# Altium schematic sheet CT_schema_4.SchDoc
size 578 x 363 mm
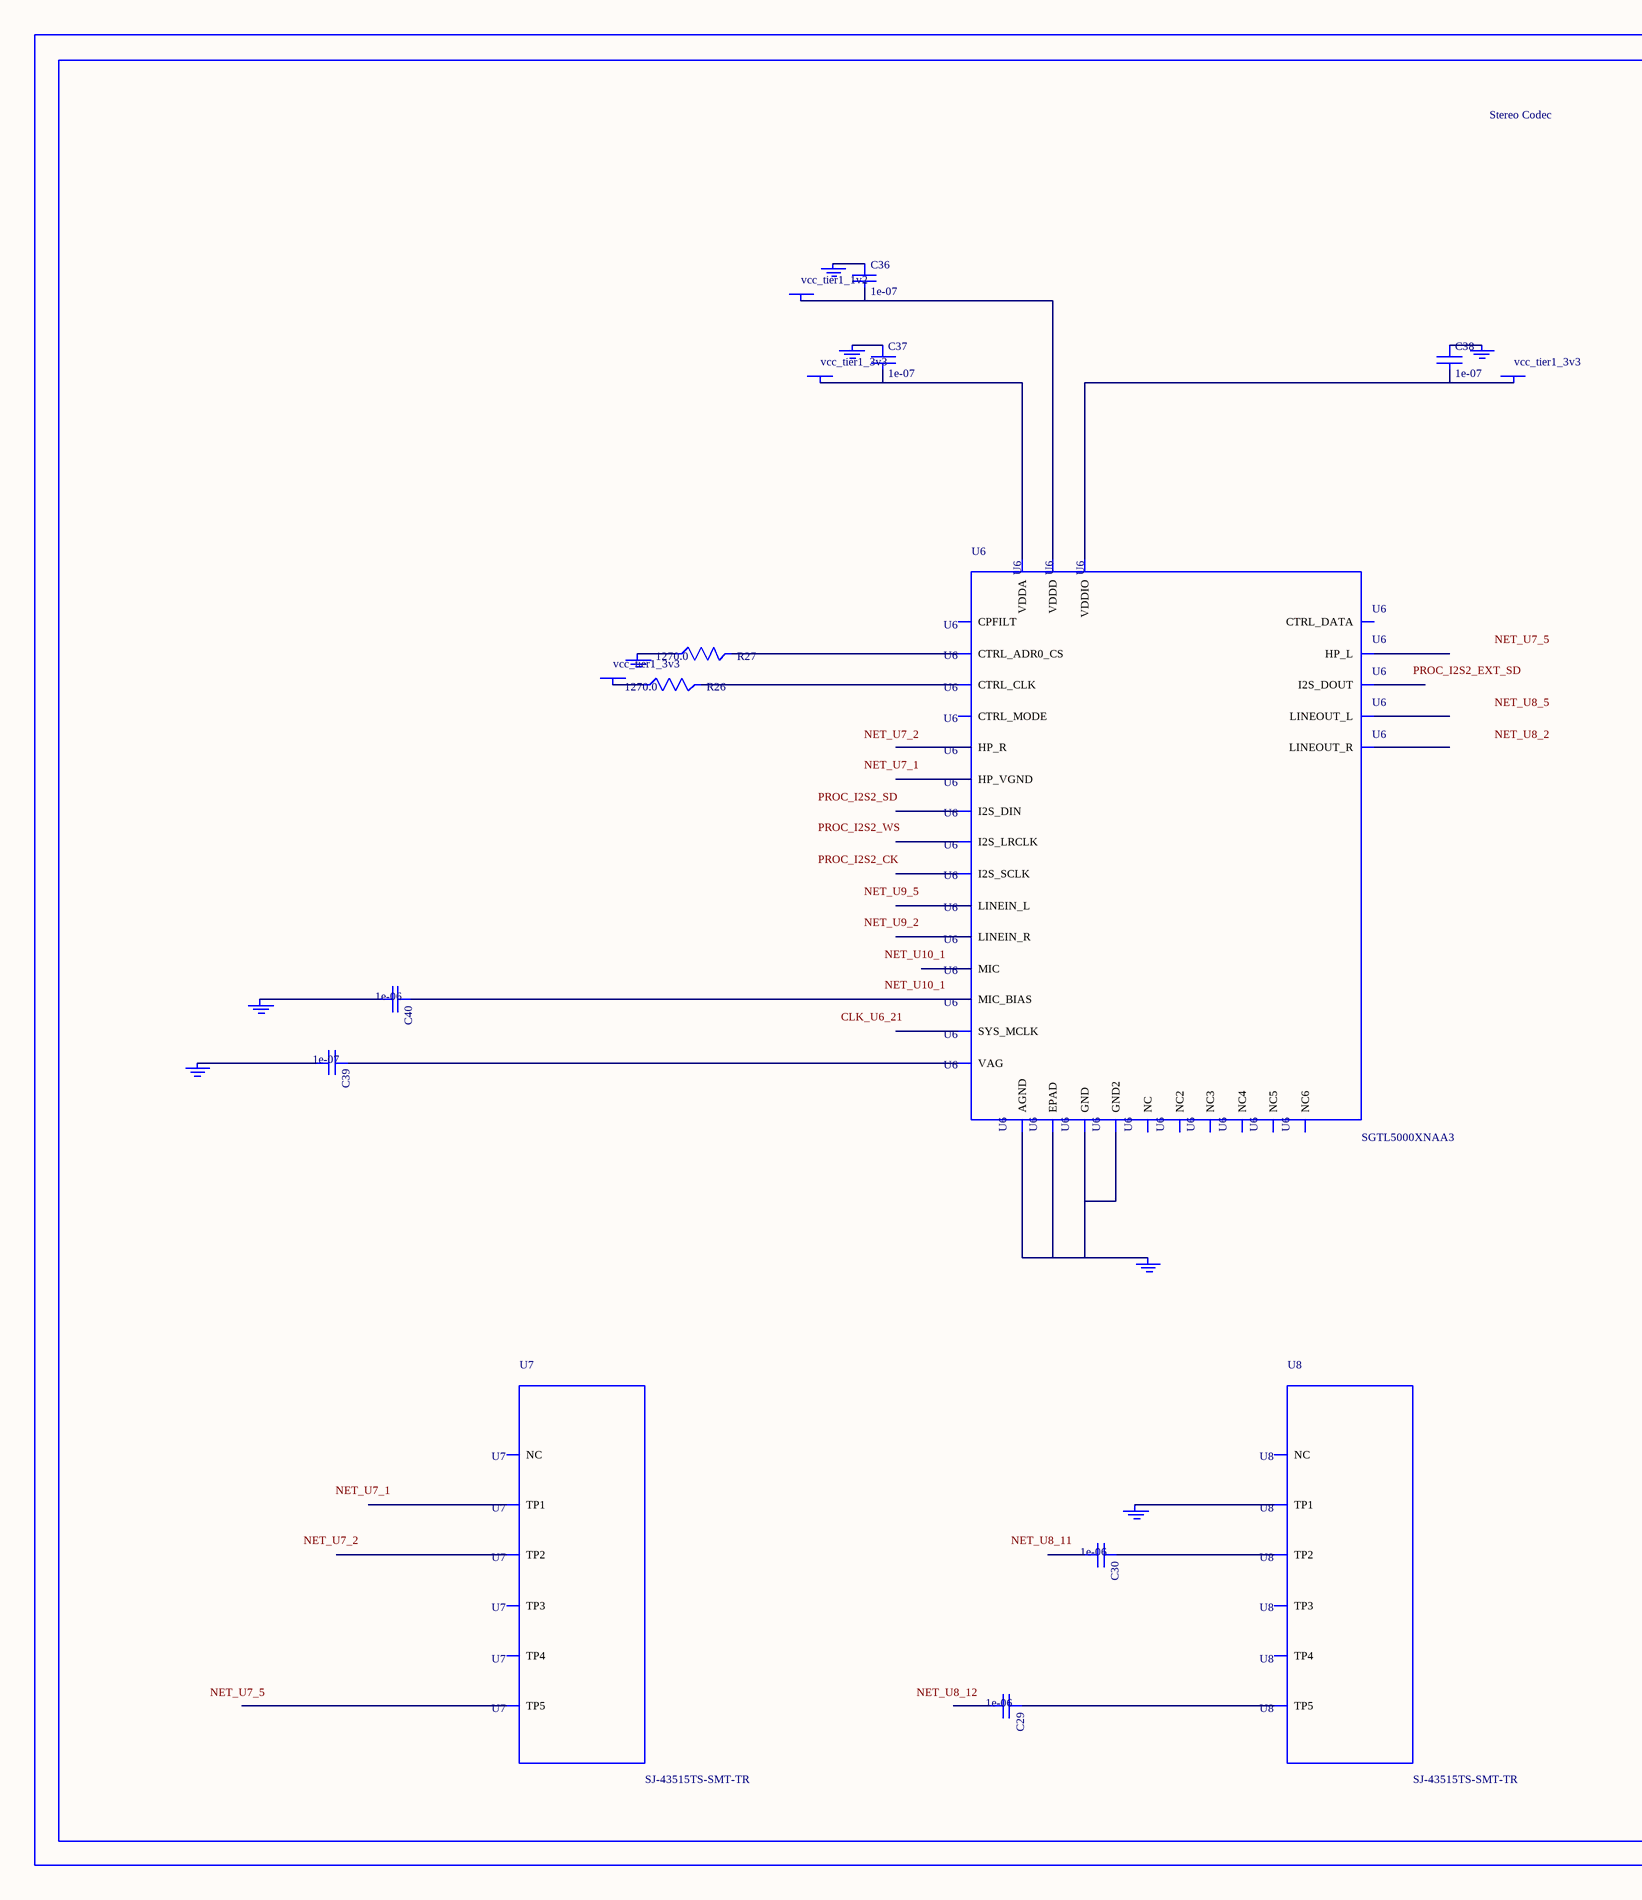
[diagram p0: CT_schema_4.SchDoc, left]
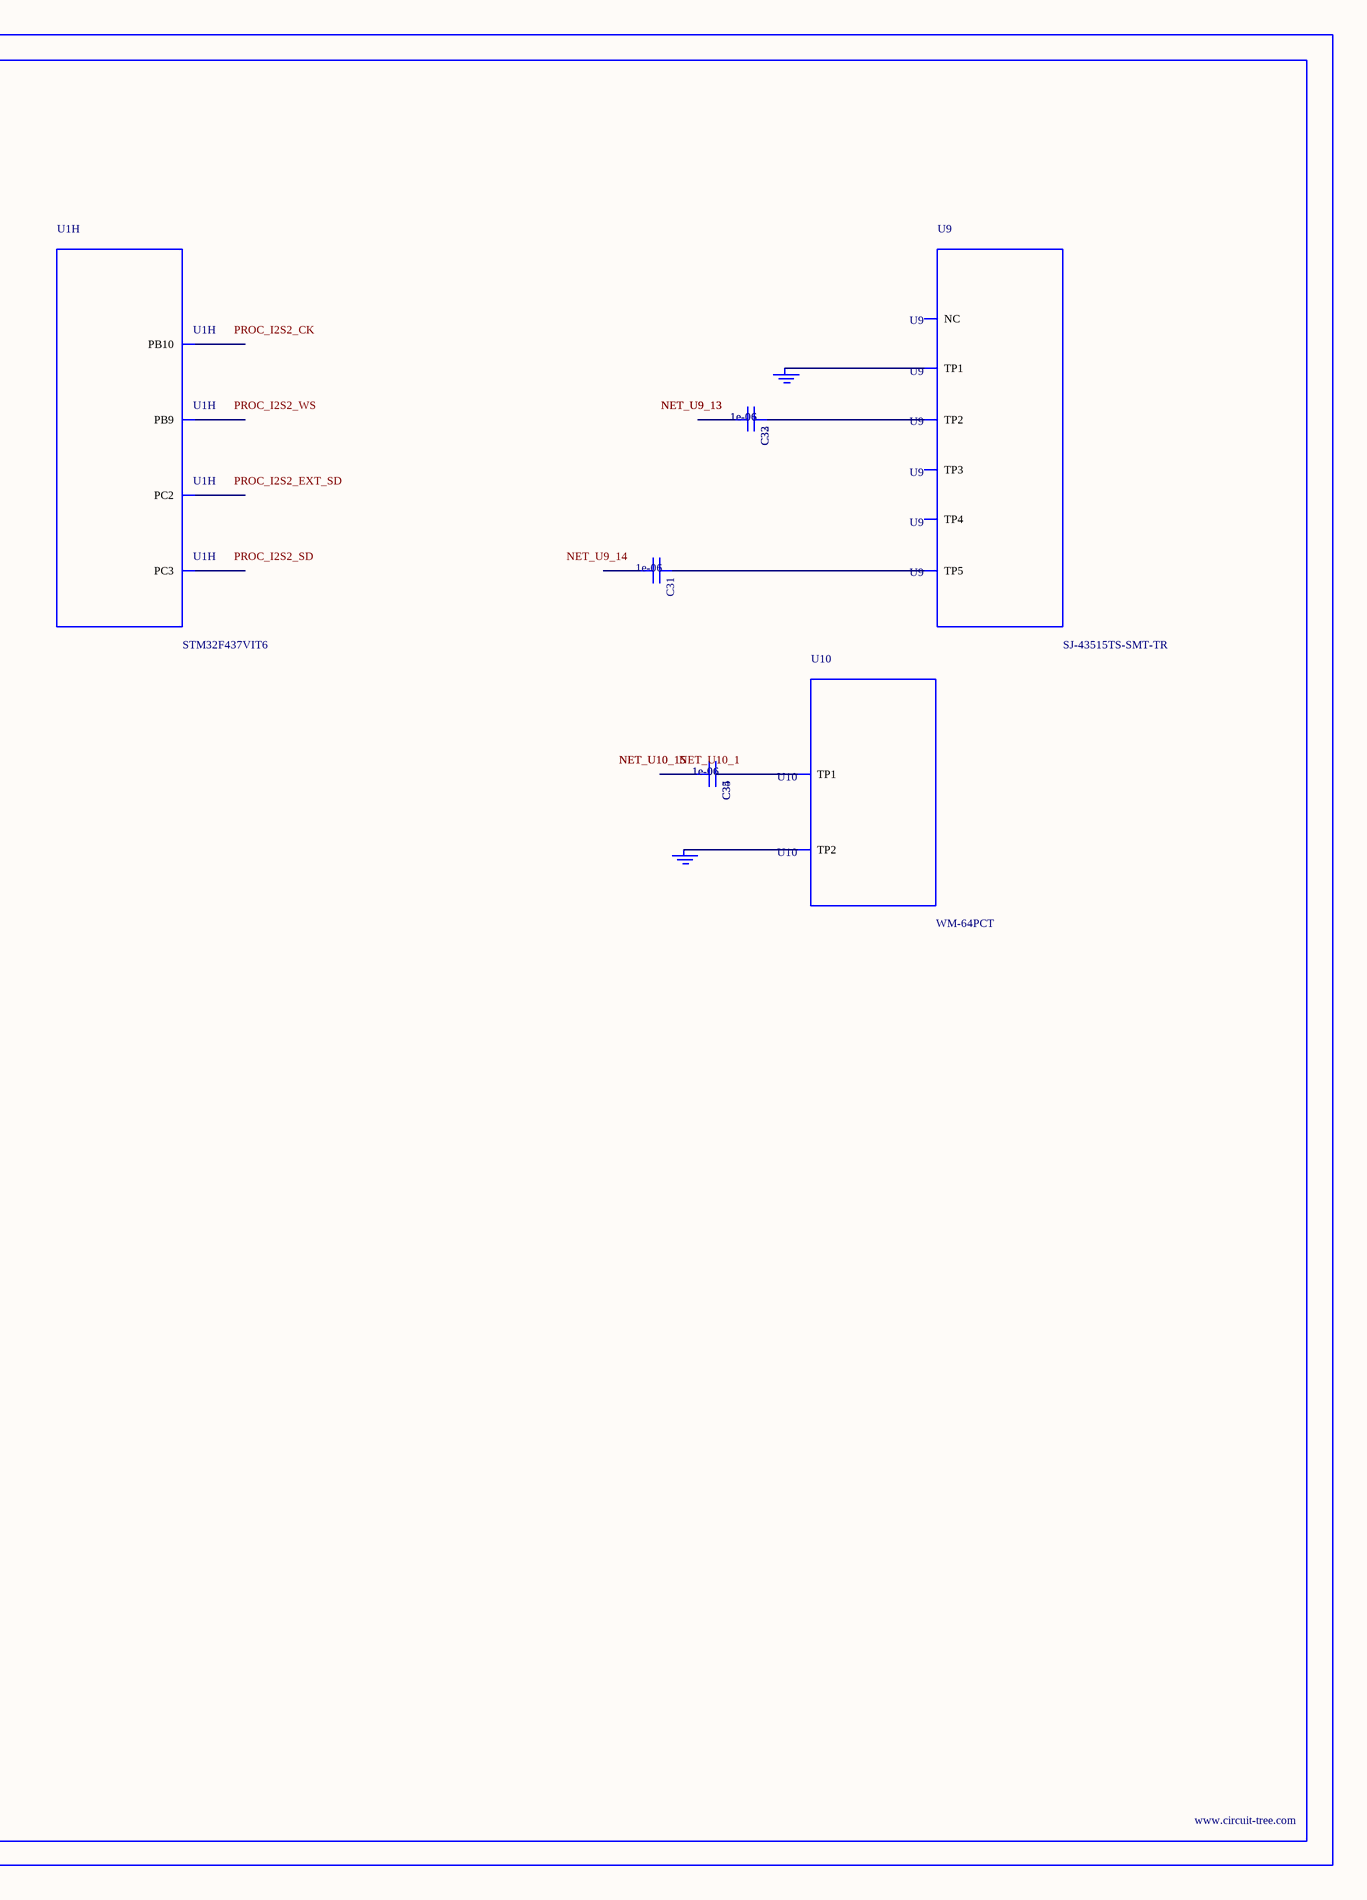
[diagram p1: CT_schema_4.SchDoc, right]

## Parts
BORDER3  (no value)
C29  1e-06  [C0603]
C30  1e-06  [C0603]
C31  1e-06  [C0603]
C32  1e-06  [C0603]
C33  1e-06  [C0603]
C34  1e-06  [C0603]
C35  1e-06  [C0603]
C36  1e-07  [C0402]
C37  1e-07  [C0402]
C38  1e-07  [C0402]
C39  1e-07  [C0402]
C40  1e-06  [C0603]
GND_INSTANCE_3_0  (no value)
GND_INSTANCE_3_1  (no value)
GND_INSTANCE_3_2  (no value)
GND_INSTANCE_3_3  (no value)
GND_INSTANCE_3_4  (no value)
GND_INSTANCE_3_5  (no value)
GND_INSTANCE_3_6  (no value)
GND_INSTANCE_3_7  (no value)
GND_INSTANCE_3_8  (no value)
GND_INSTANCE_3_9  (no value)
GND_INSTANCE_3_10  (no value)
POWER_INSTANCE_3_0  vcc_tier1_3v3
POWER_INSTANCE_3_1  vcc_tier1_3v3
POWER_INSTANCE_3_2  vcc_tier1_3v3
POWER_INSTANCE_3_3  vcc_tier1_1v2
R26  1270.0  [R0603]
R27  1270.0  [R0603]
U1  STM32F437VIT6  [LQFP100]  (part H of 9)
U6  SGTL5000XNAA3  [QFN-32]
U7  SJ-43515TS-SMT-TR  [SJ-43515TS-SMT-TR]
U8  SJ-43515TS-SMT-TR  [SJ-43515TS-SMT-TR]
U9  SJ-43515TS-SMT-TR  [SJ-43515TS-SMT-TR]
U10  WM-64PCT  [WM-64PC]

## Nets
NetC29_1: C29.1 U8.5(TP5)
NetC30_1: C30.1 U8.2(TP2)
NetC31_1: C31.1 U9.5(TP5)
NetC32_1: C32.1 C33.1 U9.2(TP2)
NetC32_2: C32.2 C33.2
NetC34_1: C34.1 C35.1 U10.1(TP1)
NetC34_2: C34.2 C35.2
NetC36_1: C36.1 GND_INSTANCE_3_5.0(GND)
NetC36_2: C36.2 POWER_INSTANCE_3_3.0(PWR) U6.30(VDDD)
NetC37_1: C37.1 GND_INSTANCE_3_1.0(GND)
NetC37_2: C37.2 POWER_INSTANCE_3_0.0(PWR) U6.5(VDDA)
NetC38_1: C38.1 GND_INSTANCE_3_4.0(GND)
NetC38_2: C38.2 POWER_INSTANCE_3_1.0(PWR) U6.20(VDDIO)
NetC39_1: C39.1 U6.10(VAG)
NetC39_2: C39.2 GND_INSTANCE_3_2.0(GND)
NetC40_1: C40.1 U6.16(MIC_BIAS)
NetC40_2: C40.2 GND_INSTANCE_3_3.0(GND)
NetGND_INSTANCE_3_0_0: GND_INSTANCE_3_0.0(GND) U6.1(GND) U6.3(GND2) U6.7(AGND) U6.EXP(EPAD)
NetGND_INSTANCE_3_6_0: GND_INSTANCE_3_6.0(GND) R27.1
NetGND_INSTANCE_3_7_0: GND_INSTANCE_3_7.0(GND) U8.1(TP1)
NetGND_INSTANCE_3_8_0: GND_INSTANCE_3_8.0(GND) GND_INSTANCE_3_9.0(GND) U9.1(TP1)
NetGND_INSTANCE_3_10_0: GND_INSTANCE_3_10.0(GND) U10.2(TP2)
NetPOWER_INSTANCE_3_2_0: POWER_INSTANCE_3_2.0(PWR) R26.1
NetR26_2: R26.2 U6.29(CTRL_CLK)
NetR27_2: R27.2 U6.31(CTRL_ADR0_CS)

Not connected (* = marked no-connect by the designer): C29 2; C30 2; C31 2; U1 17(PC2) 18(PC3) 47(PB10) 96(PB9); U6 2(HP_R) 4(HP_VGND) 6(HP_L) 8(NC) 9(NC2) 11(LINEOUT_R) 12(LINEOUT_L) 13(LINEIN_R) 14(LINEIN_L) 15(MIC) 17(NC3) 18(CPFILT) 19(NC4) 21(SYS_MCLK) 22(NC5) 23(I2S_LRCLK) 24(I2S_SCLK) 25(I2S_DOUT) 26(I2S_DIN) 27(CTRL_DATA) 28(NC6) 32(CTRL_MODE); U7 1(TP1) 2(TP2) 3(TP3) 4(TP4) 5(TP5) 6(NC); U8 3(TP3) 4(TP4) 6(NC); U9 3(TP3) 4(TP4) 6(NC)

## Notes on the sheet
- Labels drawn without touching a wire or pin: CLK_U6_21, NET_U7_1, NET_U7_2, NET_U7_5, NET_U8_2, NET_U8_5, NET_U8_11, NET_U8_12, NET_U9_2, NET_U9_5, NET_U9_14, NET_U10_1, PROC_I2S2_CK, PROC_I2S2_EXT_SD, PROC_I2S2_SD, PROC_I2S2_WS

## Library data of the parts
BORDER3 = BORDER_PAGE3
C29-C35 C40 = C0603C105K3RACTU
C36-C39 = C0402C104K3RACTU
GND_INSTANCE_3_0-GND_INSTANCE_3_10 = GND
POWER_INSTANCE_3_0-POWER_INSTANCE_3_3 = PWR
R26 R27 = RC0603FR-071K27L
